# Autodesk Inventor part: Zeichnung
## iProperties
Title: Zeichnung
Author: Schneider
Revision Number: 00
Created: 2002-08
Part Number: Z46_TSch
Material: Standard
Document SubType Name: Modellieren
Designer: Schneider
Company: Kunde
Breite: 1,000 mm
Höhe: 1,000 mm
Tiefe: 1,000 mm
Control State: 0
Master: False
Checked Out: False
Last Check In By: KSO_Schneider
Last Check In Date: 2002-08-16
PropertySet Name: Design Tracking Control
Shininess: 20.0
Angle Display Precision: 2
Document Length Units: 11269
Document Angle Units: 11283
Document Time Units: 11279
Document Mass Units: 11290
Document Length Units Precision: 3
Document Angle Units Precision: 2
Compacted: False
PropertySet Name: _Private Model Information
Density: 0.0
Volumn: 0.0
Area: 0.0
PropertySet Name: Model Information
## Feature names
1. Extrusion4
2. Extrusion5
3. Spiegeln2 [Mirror]
4. Extrusion2
5. Extrusion3
6. Spiegeln1 [Mirror]
7. Drehung1 [Revolution]
8. Rundung1 [Fillet]
9. Extrusion1
